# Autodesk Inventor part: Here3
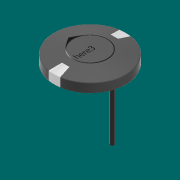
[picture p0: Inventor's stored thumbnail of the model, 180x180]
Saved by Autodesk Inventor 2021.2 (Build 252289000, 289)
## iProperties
Created: 2022-07
Part Number: Here3
Material: Generic
Document SubType Name: Modeling
Designer: Medvezh0n0k
Density: 1 g/cm^3
Appearance: Default
Author: Medvezh0n0k
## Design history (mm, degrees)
sketch "Sketch1"
  geometry: L1 (0, 10.99)-(0, -10.99) reference; L2 (-6.665, 0)-(39.99, 0) reference; L3 (0, 7.85)-(15.5, 7.85); L4 (15.5, 7.85)-(33.325, 4.35); L5 (33.325, 4.35)-(33.325, -4.35); L6 (33.325, -4.35)-(15.5, -7.85); L7 (15.5, -7.85)-(0, -7.85); L8 (0, 7.85)-(0, -7.85); 2 further points
  constraints: 12 end point, 2 horizontal, 2 midpoint, 2 point on line, 2 vertical, 1 horizontal alignment, 1 parallel
  dimensions: "d0" = 33.325 distance between parallel lines of L1 L5; "d1" = 15.7 distance between parallel lines of L7 L3; "d2" = 15.5 distance of L3.start L3.end; "d3" = 8.7 distance of L4.end L5.end
revolve "Revolution1" sketch "Sketch1" stored, may be unused: angle "d4" = 90 deg
sketch "Sketch2"
  geometry: L1 (0, 46.655)-(0, -46.655) reference; L2 (-46.655, 0)-(46.655, 0) reference; L3 (-2.3, -7.25)-(5.7, -7.25); L4 (5.7, -7.25)-(5.7, -13.75); L5 (5.7, -13.75)-(-2.3, -13.75); L6 (-2.3, -13.75)-(-2.3, -7.25); 1 further point
  constraints: 8 end point, 2 parallel, 1 horizontal, 1 perpendicular
  dimensions: "d5" = 8 distance of L4.end L5.end; "d6" = 6.5 distance of L5.end L3.start; "d7" = 7.25 distance between parallel lines of L2 L3; "d8" = 2.3 distance between parallel lines of L1 L6
extrude "Extrusion1" cut sketch "Sketch2" distance "d9" = 3.7; taper "d10" = 0 deg
mirror "Mirror1"
sketch "Sketch3"
  geometry: L1 (16.5, 5.85)-(24.5, 5.85); L2 (24.5, 5.85)-(24.5, -5.85); L3 (24.5, -5.85)-(16.5, -5.85); L4 (16.5, -5.85)-(16.5, 5.85); L5 (-46.655, 0)-(46.655, 0) reference; L6 (0, 46.655)-(0, -46.655) reference; 2 further points
  constraints: 8 end point, 2 parallel, 1 horizontal, 1 midpoint, 1 perpendicular, 1 point on line
  dimensions: "d11" = 11.7 distance of L1.end L2.end; "d12" = 8 distance of L2.end L3.end; "d13" = 16.5 distance between parallel lines of L6 L4
extrude "Extrusion2" join sketch "Sketch3" distance "d14" = 3.7; taper "d15" = 0 deg
sketch "Sketch4"
  geometry: L1 (24.5, -5.85)-(16.5, 5.85); C1 r 1.8 at (20.5, 0); 1 further point
  constraints: 2 end point, 1 centre point, 1 midpoint
  dimensions: "d16" = 3.6 diameter of C1
extrude "Extrusion3" join sketch "Sketch4" distance "d17" = 50; taper "d18" = 0 deg
fillet "Fillet1" dims "d19" = 2
fillet "Fillet2" dims "d20" = 1
sketch "Sketch5" dims "d22" = 54
  geometry: L1 (26.8, 3.4)-(26.8, 11.1) reference; C1 r 5 at (29.3, 7.25); A1 r 2 centre (24.8, 11.1) between (26.8, 11.1) and (24.8, 13.1) reference; A2 r 2 centre (24.8, 3.4) between (24.8, 1.4) and (26.8, 3.4) reference; 4 further points
  constraints: 2 horizontal alignment, 1 centre point, 1 coincident, 2 other
  dimensions: "d23" = 10 diameter of C1
extrude "Extrusion4" cut sketch "Sketch5" distance "d24" = 3.5; taper "d25" = 0 deg
sketch "Sketch6"
  geometry: C1 r 5 at (29.3, 7.25) reference; C2 r 2.45 at (29.3, 7.25); 1 further point
  constraints: 1 centre point, 1 coincident
  dimensions: "d26" = 4.9 diameter of C2
extrude "Extrusion5" join sketch "Sketch6" distance "d27" = 1.5; taper "d28" = 0 deg
chamfer "Chamfer1" distance "d29" = 1; stored, may be unused: second distance "d30" = 2, angle "d31" = 45 deg
sketch "Sketch7"
  geometry: L1 (0, 0)-(-20, 0); L2 (-20, 0)-(-13.203, 9.473); L3 (-20, 0)-(-13.203, -9.473); C1 r 15.5 at (0, 0) reference; A1 r 16.25 centre (0, 0) between (-13.203, 9.473) and (-13.203, -9.473); 1 further point
  constraints: 6 end point, 2 point on circle, 1 centre point, 1 equal length, 1 horizontal, 1 tangent
  dimensions: "d32" = 0.75 radial gap between concentric circles of A1 C1; "d33" = 20 distance of L1.start L1.end
extrude "Extrusion6" cut sketch "Sketch7" stored distance "d34" = 0.15; taper "d35" = 0 deg
sketch "Sketch8" dims "d0" = 33.325, "d1" = 15.7, "d2" = 15.5, "d3" = 8.7
  geometry: L1 (-2.595, -14.079)-(-2.595, 8.368); L2 (-2.595, 8.368)-(5.769, 8.368); L3 (5.769, 8.368)-(5.769, -14.079); L4 (5.769, -14.079)-(-2.595, -14.079); 1 further point
  constraints: 2 other
extrude "Extrusion7" cut sketch "Sketch8" distance "d36" = 0.15; taper "d37" = 0 deg
sketch "Sketch9"
  geometry: L1 (-5.5, 33.325)-(5.5, 33.325); L2 (5.5, 33.325)-(3.5, 22.325); L3 (3.5, 22.325)-(-3.5, 22.325); L4 (-3.5, 22.325)-(-5.5, 33.325); L5 (0, -47.031)-(0, 48.914) reference; C1 r 33.325 at (0, 0) reference; 3 further points
  constraints: 8 end point, 2 horizontal, 2 midpoint, 2 point on line, 1 tangent
  dimensions: "d38" = 7 distance of L2.end L3.end; "d39" = 11 distance of L1.start L1.end; "d40" = 11 distance between parallel lines of L3 L1
extrude "Extrusion8" new body sketch "Sketch9" stored distance "d41" = 20; taper "d42" = 0 deg
combine "Combine1"
combine "Combine2"
node "Direct Edit1"
pattern_circular "Circular Pattern1" dims angle "d45" = 360 deg
pattern_circular "Circular Pattern2" dims "d48" = 360 deg
combine "Combine3"
  body "Solid2"
body "Solid1"
feature "Size1" dims "d43" = -0.15
